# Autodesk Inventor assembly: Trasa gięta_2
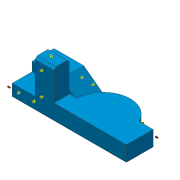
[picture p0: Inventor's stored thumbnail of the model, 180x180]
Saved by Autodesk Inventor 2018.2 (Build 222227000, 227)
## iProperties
Manager: www.cadconsulting.pl
Company: Fabian Stasiak CAD Consulting
Created: 2014-08
Part Number: Trasa gięta_2
Document SubType Name: Assembly
Designer: F.Stasiak
Catalog Web Link: www.expertbooks.pl
Author: F.Stasiak
Subject: Zbiór ćwiczeń. Autodesk Inventor 2020. Kurs Professional
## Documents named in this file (4)
- C:\ZCAI_2018_KPS\Rury\Trasa gięta_2.iam
- C:\ZCAI_2018_KPS\Rury\Konstrukcja_gięta_2.ipt
- C:\ZCAI_2018_KPS\Rury\Oczko_1.ipt
- C:\ZCAI_2018_KPS\ContentCenter\pl-PL\ASME B16.22(06)\ASME B16.22 Złączka nakrętna C x C 1_2.ipt
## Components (16 placed, 3 different names)
1. Konstrukcja_gięta_2:1 — Wstaw:1, Wstaw:2, Wstaw:3, Wstaw:4, Wstaw:5, Wstaw:6, Kąt:1, Wstaw:7, Wstaw:8, Wstaw:9, Kąt:2, Wstaw:10, Wstaw:11, Wstaw:12, Wstaw:13, Kąt:3, Zestawiający:5, Zestawiający:7
2. Oczko_1:1 — Wstaw:1, Zestawiający:1, Zestawiający:6
3. Oczko_1:2 — Wstaw:2, Zestawiający:1
4. Oczko_1:3 — Wstaw:3, Zestawiający:2
5. Oczko_1:4 — Wstaw:4, Zestawiający:2
6. Oczko_1:5 — Wstaw:5
7. Oczko_1:6 — Wstaw:6, Kąt:1
8. Oczko_1:7 — Wstaw:7, Zestawiający:3
9. Oczko_1:8 — Wstaw:8, Zestawiający:3
10. Oczko_1:9 — Wstaw:9, Kąt:2
11. Oczko_1:10 — Wstaw:10, Równoległy:3
12. Oczko_1:11 — Wstaw:12, Równoległy:1
13. Oczko_1:12 — Wstaw:11, Równoległy:2
14. Oczko_1:13 — Wstaw:13, Kąt:3, Równoległy:1, Równoległy:2, Równoległy:3, Zestawiający:4
15. ASME B16.22 Złączka nakrętna C x C 1/2:1 — Zestawiający:4, Zestawiający:5
16. ASME B16.22 Złączka nakrętna C x C 1/2:2 — Zestawiający:6, Zestawiający:7
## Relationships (26: Insert 13, Mate 7, Angle 3, Flush 3)
- Wstaw:1 [Insert]: Konstrukcja_gięta_2:1 ↔ Oczko_1:1
- Wstaw:2 [Insert]: Konstrukcja_gięta_2:1 ↔ Oczko_1:2
- Zestawiający:1 [Mate]: Oczko_1:1 ↔ Oczko_1:2
- Wstaw:3 [Insert]: Konstrukcja_gięta_2:1 ↔ Oczko_1:3
- Wstaw:4 [Insert]: Konstrukcja_gięta_2:1 ↔ Oczko_1:4
- Zestawiający:2 [Mate]: Oczko_1:3 ↔ Oczko_1:4
- Wstaw:5 [Insert]: Konstrukcja_gięta_2:1 ↔ Oczko_1:5
- Wstaw:6 [Insert]: Konstrukcja_gięta_2:1 ↔ Oczko_1:6
- Kąt:1 [Angle]: Konstrukcja_gięta_2:1 ↔ Oczko_1:6
- Wstaw:7 [Insert]: Konstrukcja_gięta_2:1 ↔ Oczko_1:7
- Wstaw:8 [Insert]: Konstrukcja_gięta_2:1 ↔ Oczko_1:8
- Zestawiający:3 [Mate]: Oczko_1:7 ↔ Oczko_1:8
- Wstaw:9 [Insert]: Konstrukcja_gięta_2:1 ↔ Oczko_1:9
- Kąt:2 [Angle]: Konstrukcja_gięta_2:1 ↔ Oczko_1:9
- Wstaw:10 [Insert]: Konstrukcja_gięta_2:1 ↔ Oczko_1:10
- Wstaw:11 [Insert]: Konstrukcja_gięta_2:1 ↔ Oczko_1:12
- Wstaw:12 [Insert]: Konstrukcja_gięta_2:1 ↔ Oczko_1:11
- Wstaw:13 [Insert]: Konstrukcja_gięta_2:1 ↔ Oczko_1:13
- Kąt:3 [Angle]: Konstrukcja_gięta_2:1 ↔ Oczko_1:13
- Równoległy:1 [Flush]: Oczko_1:11 ↔ Oczko_1:13
- Równoległy:2 [Flush]: Oczko_1:12 ↔ Oczko_1:13
- Równoległy:3 [Flush]: Oczko_1:10 ↔ Oczko_1:13
- Zestawiający:4 [Mate]: Oczko_1:13 ↔ ASME B16.22 Złączka nakrętna C x C 1/2:1
- Zestawiający:5 [Mate]: Konstrukcja_gięta_2:1 ↔ ASME B16.22 Złączka nakrętna C x C 1/2:1
- Zestawiający:6 [Mate]: Oczko_1:1 ↔ ASME B16.22 Złączka nakrętna C x C 1/2:2
- Zestawiający:7 [Mate]: Konstrukcja_gięta_2:1 ↔ ASME B16.22 Złączka nakrętna C x C 1/2:2
